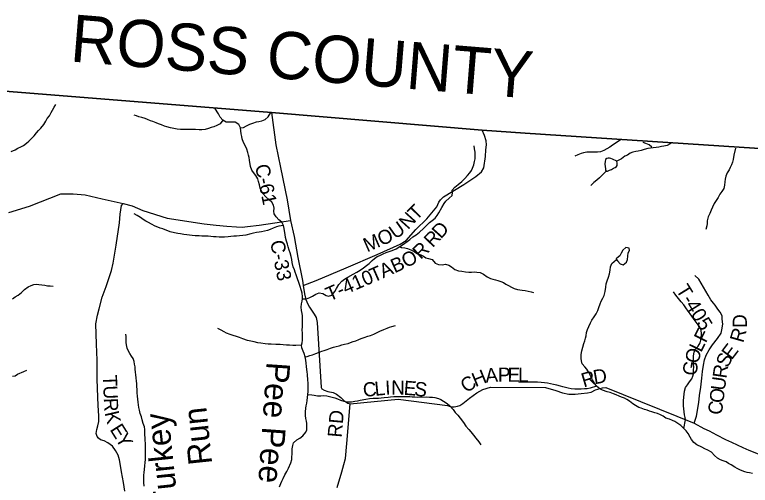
# Model space of a CAD drawing. Extents: x 1578669 to 1989827, y 208020 to 553079.
# Drawn here: x 1795443 to 1811019, y 424095 to 434061 of the extents above; entities that cross this region are included whole.
import ezdxf

# ---------------------------------------------------------------- set-up
doc = ezdxf.new("R2010")
doc.units = 0
for name, color, linetype in [('GM_X_Adjacent_County', 7, 'Continuous'), ('GM_X_Adjacent_County_Text', 7, 'Continuous'), ('GM_X_County', 7, 'Continuous'), ('GM_X_County_Road', 7, 'Continuous'), ('GM_X_County_Road_Text', 7, 'Continuous'), ('GM_X_Minor_Lake', 7, 'Continuous'), ('GM_X_Minor_River', 7, 'Continuous'), ('GM_X_Minor_River_Text', 7, 'Continuous'), ('GM_X_Township', 7, 'Continuous'), ('GM_X_Township_Road', 7, 'Continuous'), ('GM_X_Township_Road_Text', 7, 'Continuous')]:
    doc.layers.add(name, color=color, linetype=linetype)

msp = doc.modelspace()

# ---------------------------------------------------------------- linework, layer by layer
at = {"layer": 'GM_X_Adjacent_County'}
msp.add_lwpolyline([(1849204, 428734), (1845065, 429025), (1838434, 429477), (1835610, 429648), (1834516, 429711), (1833780, 429762), (1832918, 429813), (1828657, 430067), (1826767, 430168), (1822276, 430466), (1822111, 430472), (1818512, 430701), (1815260, 430933), (1812296, 431154), (1806251, 431556), (1805343, 431619), (1800878, 431987), (1794614, 432491)], dxfattribs=at)
at = {"layer": 'GM_X_County'}
msp.add_lwpolyline([(1794614, 432491), (1800878, 431987), (1805343, 431619), (1806251, 431556), (1812296, 431154), (1815260, 430933), (1818512, 430701), (1822111, 430472), (1822276, 430466), (1826767, 430168), (1828657, 430067), (1832918, 429813), (1833780, 429762), (1834516, 429711), (1835610, 429648), (1838434, 429477), (1845065, 429025), (1849204, 428734)], dxfattribs=at)
at = {"layer": 'GM_X_County_Road'}
for points in [[(1800878, 431987), (1800971, 431306), (1801072, 430825), (1801210, 430141), (1801283, 429700)], [(1795320, 429874), (1795754, 430005), (1796421, 430266), (1796599, 430271), (1796679, 430271), (1796937, 430244), (1797298, 430164), (1797739, 430061), (1797927, 430013), (1798153, 429916), (1798670, 429755), (1799457, 429631), (1799711, 429604), (1799934, 429584), (1800136, 429567), (1800260, 429559), (1800374, 429574), (1800621, 429604), (1801283, 429700)], [(1801283, 429700), (1801358, 429363), (1801440, 428920), (1801537, 428435), (1801549, 428324), (1801580, 428148), (1801606, 428032), (1801650, 427929), (1801685, 427865), (1801785, 427719), (1801823, 427648), (1801851, 427542), (1801935, 426167), (1801949, 426141), (1801999, 426109), (1802073, 426080), (1802183, 426062), (1802255, 426024), (1802351, 425953), (1802413, 425891), (1802495, 425835), (1802545, 425821), (1803561, 425916), (1804604, 425786), (1804680, 425756), (1804750, 425754), (1804817, 425770), (1804869, 425787), (1804931, 425829), (1805076, 425939), (1805226, 426051), (1805359, 426125), (1805517, 426172), (1806685, 426163), (1806901, 426106), (1807046, 426054), (1807180, 426025), (1807308, 426023), (1807438, 426036), (1807572, 426056), (1807651, 426070), (1807745, 426116), (1807837, 426145), (1807893, 426159), (1807962, 426163), (1809833, 425408), (1810039, 425299), (1810149, 425251), (1810301, 425164), (1810495, 425068), (1810621, 425009), (1810859, 424898), (1810991, 424838), (1811295, 424721)], [(1802269, 424048), (1802370, 424380), (1802412, 424536), (1802449, 424660), (1802474, 424983), (1802545, 425821)]]:
    msp.add_lwpolyline(points, dxfattribs=at)
at = {"layer": 'GM_X_Minor_Lake'}
for points in [[(1808190, 430963), (1808166, 430977), (1808132, 430987), (1808100, 430999), (1808069, 431016), (1808039, 431022), (1808011, 431020), (1807979, 431015), (1807955, 430997), (1807948, 430951), (1807942, 430903), (1807943, 430843), (1807955, 430803), (1807953, 430769), (1807971, 430751), (1807996, 430747), (1808037, 430769), (1808081, 430784), (1808125, 430808), (1808159, 430825), (1808187, 430847), (1808201, 430871), (1808203, 430917)], [(1808203, 430917), (1808190, 430963)], [(1808205, 428847), (1808261, 428782), (1808328, 428764), (1808401, 428821), (1808419, 428875), (1808424, 428948), (1808436, 429016), (1808463, 429068), (1808453, 429118), (1808387, 429130), (1808321, 429077), (1808288, 429008), (1808258, 428958), (1808196, 428907)], [(1808196, 428907), (1808179, 428893), (1808177, 428887), (1808186, 428878), (1808205, 428847)]]:
    msp.add_lwpolyline(points, dxfattribs=at)
at = {"layer": 'GM_X_Minor_River'}
for points in [[(1795371, 431162), (1795453, 431201), (1795511, 431232), (1795569, 431260), (1795631, 431293), (1795691, 431340), (1795742, 431380), (1795794, 431431), (1795852, 431495), (1795901, 431558), (1795949, 431609), (1795997, 431661), (1796058, 431736), (1796100, 431806), (1796133, 431861), (1796177, 431921), (1796214, 431988), (1796244, 432042), (1796279, 432101), (1796315, 432161)], [(1800378, 431146), (1800358, 431216), (1800327, 431274), (1800284, 431354), (1800260, 431432), (1800251, 431484), (1800239, 431540), (1800232, 431600), (1800227, 431666), (1800189, 431738), (1800112, 431783), (1800046, 431784), (1799976, 431784), (1799922, 431789), (1799851, 431826), (1799796, 431892), (1799756, 431962), (1799683, 432085)], [(1800227, 431666), (1800284, 431670), (1800349, 431705), (1800421, 431742), (1800487, 431766), (1800561, 431791), (1800613, 431802), (1800679, 431816), (1800749, 431845), (1800813, 431898), (1800867, 431990)], [(1799851, 431826), (1799794, 431750), (1799726, 431717), (1799662, 431688), (1799604, 431670), (1799548, 431651), (1799476, 431628), (1799406, 431620), (1799352, 431621), (1799269, 431628), (1799215, 431630), (1799143, 431631), (1799071, 431629), (1799017, 431628), (1798950, 431629), (1798882, 431639), (1798742, 431669), (1798667, 431687), (1798615, 431700), (1798551, 431726), (1798490, 431751), (1798436, 431775), (1798371, 431798), (1798319, 431816), (1798257, 431841), (1798202, 431861), (1798138, 431882), (1798074, 431902), (1798020, 431919), (1797969, 431933)], [(1808273, 431409), (1808157, 431332), (1808105, 431295), (1808043, 431258), (1807985, 431220), (1807920, 431189), (1807850, 431160), (1807781, 431150), (1807709, 431151), (1807657, 431153), (1807607, 431152), (1807555, 431148), (1807487, 431137), (1807437, 431122), (1807365, 431094), (1807303, 431065)], [(1809337, 431332), (1809262, 431290), (1809190, 431276), (1809138, 431267), (1809086, 431255), (1809024, 431246), (1808964, 431239), (1808904, 431235), (1808848, 431226), (1808774, 431209), (1808710, 431189), (1808646, 431172), (1808596, 431162), (1808529, 431147), (1808477, 431128), (1808416, 431090), (1808362, 431063), (1808292, 431008), (1808190, 430963)], [(1808932, 431253), (1808875, 431303), (1808809, 431334), (1808748, 431354)], [(1801536, 428043), (1801621, 428042), (1801693, 428071), (1801747, 428099), (1801822, 428144), (1801892, 428173), (1801967, 428159), (1802041, 428116), (1802091, 428103), (1802157, 428125), (1802221, 428196), (1802256, 428262), (1802306, 428349), (1802369, 428418), (1802427, 428461), (1802495, 428505), (1802611, 428565), (1802691, 428609), (1802756, 428650), (1802826, 428701), (1802894, 428748), (1802946, 428792), (1803009, 428855), (1803065, 428900), (1803117, 428938), (1803175, 428965), (1803243, 428996), (1803311, 429022), (1803374, 429047), (1803438, 429068), (1803520, 429102), (1803596, 429149), (1803674, 429202), (1803754, 429261), (1803809, 429300), (1803875, 429354), (1803945, 429403), (1804015, 429456), (1804096, 429533), (1804162, 429600), (1804229, 429660), (1804281, 429701), (1804349, 429756), (1804390, 429812), (1804426, 429867), (1804485, 429979), (1804535, 430062), (1804572, 430113), (1804646, 430177), (1804704, 430230), (1804711, 430294), (1804705, 430348), (1804762, 430407), (1804834, 430462), (1804911, 430527), (1804975, 430593), (1805033, 430658), (1805080, 430711), (1805118, 430761), (1805140, 430813), (1805165, 430882), (1805182, 430956), (1805192, 431012), (1805195, 431099), (1805191, 431149), (1805180, 431219), (1805172, 431287)], [(1810704, 431232), (1810672, 431084), (1810654, 430995), (1810641, 430935), (1810625, 430881), (1810596, 430824), (1810570, 430774), (1810528, 430714), (1810499, 430641), (1810484, 430579), (1810478, 430525), (1810471, 430448), (1810457, 430378), (1810416, 430314), (1810378, 430261), (1810337, 430187), (1810297, 430130), (1810257, 430064), (1810216, 429985), (1810189, 429919), (1810161, 429850), (1810130, 429782), (1810108, 429699), (1810103, 429641), (1810097, 429587), (1810076, 429509)], [(1801313, 424692), (1801319, 424762), (1801318, 424814), (1801320, 424868), (1801331, 424938), (1801349, 424997), (1801416, 425058), (1801480, 425096), (1801546, 425143), (1801609, 425218), (1801627, 425268), (1801632, 425346), (1801630, 425402), (1801619, 425456), (1801609, 425512), (1801598, 425574), (1801600, 425649), (1801611, 425729), (1801618, 425779), (1801628, 425837), (1801635, 425891), (1801645, 425958), (1801652, 426016), (1801660, 426080), (1801659, 426198), (1801654, 426264), (1801650, 426325), (1801641, 426441), (1801636, 426497), (1801630, 426551), (1801623, 426609), (1801615, 426679), (1801606, 426745), (1801593, 426815), (1801569, 426887), (1801550, 426939), (1801521, 427009), (1801515, 427061), (1801531, 427115), (1801538, 427169), (1801536, 427235), (1801535, 427320), (1801532, 427390), (1801536, 427450), (1801537, 427516), (1801539, 427572), (1801538, 427632), (1801534, 427682), (1801527, 427736), (1801519, 427796), (1801512, 427868), (1801519, 427939), (1801531, 427993), (1801536, 428043), (1801536, 428095), (1801527, 428161), (1801513, 428213), (1801480, 428325), (1801459, 428393), (1801432, 428471), (1801404, 428555), (1801385, 428607), (1801365, 428659), (1801342, 428721), (1801321, 428815), (1801309, 428875), (1801294, 428941), (1801273, 429015), (1801253, 429075), (1801232, 429142), (1801216, 429204), (1801197, 429268), (1801180, 429340), (1801172, 429406), (1801159, 429484), (1801152, 429534), (1801134, 429600), (1801099, 429666), (1801037, 429720), (1800978, 429783), (1800937, 429847), (1800933, 429901), (1800936, 429963), (1800924, 430029), (1800885, 430089), (1800830, 430143), (1800760, 430204), (1800699, 430272), (1800662, 430335), (1800640, 430387), (1800623, 430461), (1800608, 430527), (1800592, 430585), (1800547, 430653), (1800496, 430717), (1800466, 430770), (1800437, 430848), (1800416, 430984), (1800405, 431036), (1800395, 431086), (1800378, 431146)], [(1807971, 430751), (1807878, 430656), (1807826, 430605), (1807773, 430558), (1807705, 430506), (1807643, 430447)], [(1801134, 429600), (1801036, 429581), (1800984, 429571), (1800916, 429542), (1800850, 429514), (1800796, 429493), (1800734, 429476), (1800668, 429464), (1800616, 429459), (1800562, 429449), (1800498, 429434), (1800442, 429419), (1800334, 429390), (1800270, 429382), (1800203, 429377), (1800141, 429374), (1800081, 429370), (1800019, 429363), (1799961, 429359), (1799885, 429352), (1799829, 429351), (1799770, 429353), (1799706, 429354), (1799650, 429360), (1799598, 429365), (1799540, 429369), (1799488, 429372), (1799407, 429373), (1799347, 429377), (1799265, 429380), (1799199, 429385), (1799145, 429391), (1799084, 429400), (1799026, 429408), (1798954, 429419), (1798896, 429429), (1798825, 429442), (1798735, 429463), (1798683, 429483), (1798632, 429502), (1798576, 429524), (1798522, 429543), (1798471, 429563), (1798419, 429586), (1798338, 429628), (1798274, 429663), (1798220, 429691), (1798163, 429726), (1798105, 429764), (1798036, 429811), (1797974, 429847)], [(1803596, 429149), (1803634, 429128), (1803705, 429122), (1803759, 429109), (1803831, 429085), (1803902, 429048), (1803970, 428995), (1804045, 428977), (1804101, 428948), (1804152, 428912), (1804208, 428901), (1804280, 428877), (1804349, 428800), (1804420, 428774), (1804494, 428763), (1804564, 428778), (1804638, 428760), (1804689, 428719), (1804763, 428665), (1804842, 428640), (1804914, 428633), (1804988, 428618), (1805057, 428606), (1805113, 428609), (1805179, 428613), (1805229, 428612), (1805297, 428599), (1805370, 428565), (1805446, 428510), (1805515, 428476), (1805565, 428461), (1805624, 428445), (1805676, 428432), (1805738, 428414), (1805792, 428391), (1805845, 428355), (1805899, 428328), (1805962, 428292), (1806016, 428263), (1806088, 428245), (1806139, 428238), (1806191, 428230), (1806251, 428219), (1806315, 428208), (1806376, 428194), (1806426, 428177)], [(1807597, 427460), (1807637, 427539), (1807664, 427591), (1807710, 427662), (1807753, 427728), (1807789, 427797), (1807814, 427863), (1807840, 427940), (1807865, 427998), (1807897, 428057), (1807922, 428117), (1807948, 428201), (1807957, 428290), (1807970, 428362), (1807992, 428426), (1808019, 428505), (1808041, 428575), (1808052, 428649), (1808059, 428720), (1808085, 428792), (1808185, 428880)], [(1795397, 428044), (1795455, 428085), (1795518, 428121), (1795588, 428178), (1795650, 428239), (1795727, 428298), (1795789, 428328), (1795847, 428347), (1795899, 428352), (1795955, 428348), (1796014, 428343), (1796078, 428333), (1796140, 428322), (1796190, 428316), (1796259, 428309)], [(1809615, 425299), (1809646, 425482), (1809639, 425534), (1809629, 425584), (1809618, 425650), (1809610, 425716), (1809607, 425778), (1809605, 425834), (1809604, 425887), (1809610, 425965), (1809617, 426025), (1809628, 426091), (1809650, 426166), (1809691, 426220), (1809733, 426283), (1809781, 426353), (1809802, 426404), (1809814, 426458), (1809819, 426532), (1809822, 426606), (1809820, 426664), (1809819, 426730), (1809815, 426785), (1809816, 426837), (1809828, 426913), (1809861, 426975), (1809915, 427044), (1809956, 427111), (1809974, 427169), (1809981, 427225), (1809987, 427299), (1809976, 427385), (1809939, 427467), (1809874, 427549), (1809834, 427610), (1809785, 427678), (1809744, 427730), (1809706, 427782), (1809655, 427851), (1809613, 427915), (1809558, 427979), (1809497, 428054), (1809442, 428124), (1809392, 428189)], [(1801593, 426815), (1801639, 426822), (1801695, 426842), (1801749, 426859), (1801817, 426887), (1801873, 426910), (1801943, 426935), (1801999, 426953), (1802057, 426974), (1802131, 426999), (1802195, 427019), (1802249, 427036), (1802313, 427050), (1802371, 427067), (1802427, 427082), (1802501, 427100), (1802555, 427117), (1802611, 427140), (1802663, 427158), (1802729, 427185), (1802781, 427203), (1802841, 427226), (1802919, 427253), (1802975, 427271), (1803045, 427298), (1803105, 427323), (1803177, 427359), (1803259, 427396), (1803329, 427423), (1803382, 427444), (1803432, 427458), (1803506, 427481)], [(1811069, 424348), (1811001, 424359), (1810951, 424368), (1810901, 424380), (1810814, 424415), (1810740, 424453), (1810689, 424482), (1810617, 424528), (1810560, 424559), (1810506, 424589), (1810445, 424614), (1810387, 424634), (1810325, 424667), (1810262, 424726), (1810195, 424796), (1810117, 424841), (1810060, 424867), (1809992, 424900), (1809891, 424951), (1809826, 425005), (1809778, 425062), (1809745, 425114), (1809703, 425190), (1809660, 425248), (1809615, 425299), (1809551, 425363), (1809488, 425406), (1809420, 425444), (1809369, 425465), (1809307, 425493), (1809230, 425518), (1809176, 425556), (1809116, 425587), (1809055, 425613), (1808999, 425632), (1808934, 425654), (1808884, 425667), (1808834, 425685), (1808780, 425700), (1808709, 425726), (1808659, 425741), (1808586, 425782), (1808530, 425822), (1808461, 425879), (1808405, 425911), (1808354, 425937), (1808294, 425964), (1808244, 425986), (1808177, 426013), (1808121, 426032), (1808053, 426058), (1807992, 426073), (1807892, 426112), (1807835, 426140), (1807763, 426193), (1807720, 426259), (1807675, 426331), (1807636, 426411), (1807602, 426482), (1807561, 426552), (1807516, 426604), (1807460, 426671), (1807447, 426729), (1807439, 426783), (1807440, 426868), (1807451, 426940), (1807473, 427018), (1807498, 427101), (1807516, 427153), (1807529, 427209), (1807543, 427263), (1807554, 427328), (1807572, 427394), (1807597, 427460)], [(1797802, 427246), (1797793, 427296)], [(1801515, 427061), (1801399, 427056), (1801329, 427057), (1801262, 427062), (1801198, 427066), (1801124, 427071), (1801062, 427074), (1800969, 427080), (1800875, 427083), (1800809, 427086), (1800743, 427093), (1800656, 427103), (1800590, 427114), (1800514, 427133), (1800445, 427149), (1800373, 427164), (1800275, 427195), (1800206, 427223), (1800140, 427246), (1800067, 427269), (1800005, 427291), (1799931, 427320), (1799880, 427346), (1799812, 427383), (1799747, 427419)], [(1798184, 424076), (1798176, 424154), (1798175, 424227), (1798178, 424309), (1798186, 424369), (1798191, 424427), (1798199, 424509), (1798204, 424580), (1798210, 424644), (1798213, 424712), (1798212, 424770), (1798214, 424858), (1798213, 424925), (1798211, 424987), (1798208, 425041), (1798204, 425105), (1798201, 425159), (1798201, 425221), (1798196, 425275), (1798188, 425333), (1798165, 425407), (1798142, 425483), (1798126, 425543), (1798101, 425615), (1798084, 425683), (1798070, 425743), (1798061, 425801), (1798055, 425857), (1798050, 425921), (1798043, 425985), (1798039, 426055), (1798034, 426127), (1798032, 426190), (1798027, 426254), (1798023, 426304), (1798016, 426372), (1798009, 426432), (1798003, 426494), (1797996, 426552), (1797990, 426606), (1797981, 426664), (1797971, 426716), (1797950, 426778), (1797918, 426830), (1797879, 426884), (1797851, 426937), (1797824, 426997), (1797807, 427069), (1797803, 427119), (1797804, 427183), (1797802, 427246)], [(1795397, 426403), (1795451, 426415), (1795505, 426446), (1795633, 426507), (1795699, 426536)], [(1807763, 426193), (1807631, 426150), (1807563, 426137), (1807507, 426135), (1807438, 426132), (1807380, 426129), (1807304, 426129), (1807228, 426140), (1807161, 426155), (1807107, 426167), (1807051, 426180), (1807001, 426194), (1806926, 426215), (1806850, 426233), (1806792, 426246), (1806723, 426257), (1806659, 426267), (1806593, 426274), (1806513, 426277), (1806453, 426281), (1806386, 426280), (1806330, 426282), (1806260, 426279), (1806186, 426278), (1806120, 426274)], [(1801652, 426016), (1801733, 426013), (1801787, 426005), (1801857, 425990), (1801925, 425992), (1801987, 425995), (1802054, 425988), (1802108, 425976), (1802164, 425963), (1802221, 425947), (1802275, 425926), (1802345, 425896), (1802412, 425877), (1802476, 425866), (1802572, 425866), (1802642, 425877), (1802704, 425884), (1802760, 425896), (1802876, 425917), (1802957, 425930), (1803035, 425937), (1803085, 425940), (1803145, 425944), (1803205, 425951), (1803267, 425957), (1803349, 425964), (1803401, 425969), (1803472, 425973), (1803536, 425974), (1803610, 425977), (1803678, 425977), (1803742, 425976), (1803808, 425973), (1803859, 425967), (1803917, 425966), (1803977, 425964), (1804171, 425966), (1804226, 425965), (1804288, 425963), (1804340, 425958), (1804416, 425936), (1804469, 425911), (1804523, 425879), (1804598, 425828), (1804648, 425786), (1804729, 425701), (1804772, 425639), (1804826, 425582), (1804879, 425514), (1804944, 425426), (1804999, 425347), (1805060, 425279), (1805100, 425225), (1805161, 425158), (1805208, 425092), (1805270, 425017), (1805315, 424951)], [(1801050, 424066), (1801075, 424132), (1801097, 424183), (1801125, 424237), (1801166, 424316), (1801207, 424390), (1801239, 424459), (1801290, 424571), (1801308, 424640), (1801313, 424692)]]:
    msp.add_lwpolyline(points, dxfattribs=at)
at = {"layer": 'GM_X_Township'}
msp.add_lwpolyline([(1794614, 432491), (1800878, 431987), (1805343, 431619), (1806251, 431556), (1812296, 431154), (1812748, 423763), (1812981, 420551), (1813183, 417646), (1813169, 417495), (1813101, 417318), (1811396, 411352), (1811003, 410233), (1810653, 409191), (1809037, 404233), (1808867, 403681), (1808758, 403152), (1808680, 402775), (1808603, 402344), (1807250, 395261), (1804835, 395344), (1793085, 395748)], dxfattribs=at)
at = {"layer": 'GM_X_Township_Road'}
for points in [[(1801549, 428324), (1801827, 428430), (1802459, 428700), (1803116, 428985), (1803605, 429204), (1803732, 429282), (1803939, 429514), (1804168, 429739), (1804379, 429991), (1804421, 430089), (1804456, 430139), (1804526, 430203), (1804952, 430462), (1805208, 430632), (1805329, 430736), (1805375, 430818), (1805414, 431056), (1805421, 431200), (1805433, 431303), (1805426, 431388), (1805392, 431505), (1805343, 431619)], [(1797776, 423969), (1797743, 424151), (1797705, 424380), (1797682, 424516), (1797662, 424633), (1797632, 424733), (1797579, 424833), (1797511, 424922), (1797417, 424996), (1797337, 425034), (1797261, 425061), (1797217, 425091), (1797189, 425129), (1797167, 425191), (1797181, 425275), (1797204, 425358), (1797224, 425446), (1797226, 425566), (1797213, 425784), (1797201, 425959), (1797191, 426346), (1797186, 426746), (1797177, 427081), (1797158, 427514), (1797196, 427700), (1797233, 427829), (1797298, 428076), (1797379, 428308), (1797492, 428641), (1797529, 428797), (1797588, 429179), (1797664, 429653), (1797674, 429836), (1797707, 430018), (1797739, 430061)], [(1809833, 425408), (1809881, 425556), (1809928, 425849), (1809943, 425999), (1809969, 426173), (1809992, 426362), (1810010, 426502), (1810031, 426640), (1810053, 426752), (1810086, 426852), (1810150, 426962), (1810222, 427072), (1810327, 427206), (1810402, 427316), (1810418, 427386), (1810436, 427505), (1810427, 427613), (1810425, 427681), (1810383, 427759), (1810335, 427822), (1810273, 427912), (1810237, 427950), (1810185, 428024), (1810124, 428125), (1810026, 428293), (1809928, 428460), (1809844, 428540)]]:
    msp.add_lwpolyline(points, dxfattribs=at)

# ---------------------------------------------------------------- texts
at = {"layer": 'GM_X_Adjacent_County_Text'}
msp.add_text('ROSS COUNTY', height=1000, rotation=355.3774, dxfattribs=at).set_placement((1796599, 433073))
at = {"layer": 'GM_X_County_Road_Text'}
for s, rotation, p in [('C-61', 281.7823, (1800530, 430865)), ('C-33', 281.0414, (1800850, 429257)), ('H', 22.2749, (1805198, 426172)), ('A', 4.6717, (1805419, 426267)), ('P', 359.8907, (1805675, 426288)), ('E', 359.7429, (1805878, 426288)), ('L', 359.7441, (1806102, 426287)), ('R', 16.429, (1807492, 426166)), ('D', 10.1654, (1807720, 426233)), ('C', 35.4537, (1805013, 426038)), ('C', 5.3764, (1802830, 425966)), ('L', 5.3764, (1803075, 425989)), ('I', 3.3804, (1803296, 426010)), ('N', 359.3883, (1803414, 426017)), ('E', 355.3963, (1803672, 426014)), ('S', 353.4002, (1803893, 425996)), ('RD', 85.0738, (1802366, 425099))]:
    msp.add_text(s, height=300, rotation=rotation, dxfattribs=at).set_placement(p)
at = {"layer": 'GM_X_Minor_River_Text'}
for s, rotation, p in [('Pee Pee', 265.9803, (1800780, 426717)), ('Run', 95.9994, (1799626, 424551)), ('Turkey', 95.9992, (1798907, 423617))]:
    msp.add_text(s, height=500, rotation=rotation, dxfattribs=at).set_placement(p)
at = {"layer": 'GM_X_Township_Road_Text'}
for s, rotation, p in [('T', 45.1606, (1803947, 429688)), ('N', 47.8531, (1803773, 429495)), ('U', 35.2155, (1803503, 429295)), ('D', 48.0662, (1804469, 429300)), ('O', 23.6879, (1803204, 429157)), ('R', 46.5098, (1804293, 429114)), ('M', 23.5639, (1802905, 429026)), ('R', 43.562, (1804039, 428866)), ('O', 27.1557, (1803728, 428691)), ('B', 24.137, (1803487, 428583)), ('T', 23.6392, (1803038, 428385)), ('A', 23.7164, (1803244, 428476)), ('T-410', 23.3083, (1802107, 427985)), ('T-405', 301.7018, (1809435, 428235)), ('D', 90.3679, (1810948, 427429)), ('F', 62.8633, (1810077, 427094)), ('R', 73.8954, (1810867, 427099)), ('O', 74.3043, (1809912, 426654)), ('L', 63.6132, (1809978, 426894)), ('E', 52.6441, (1810624, 426736)), ('S', 63.9173, (1810543, 426568)), ('G', 81.9008, (1809877, 426403)), ('R', 81.6888, (1810515, 426347)), ('T', 272.3492, (1797308, 426427)), ('U', 82.2171, (1810479, 426087)), ('U', 272.3488, (1797317, 426203)), ('O', 83.3932, (1810449, 425826)), ('R', 272.3307, (1797328, 425939)), ('C', 81.7164, (1810412, 425573)), ('K', 283.1632, (1797346, 425632)), ('E', 302.185, (1797448, 425277)), ('Y', 299.8773, (1797565, 425090))]:
    msp.add_text(s, height=300, rotation=rotation, dxfattribs=at).set_placement(p)

doc.saveas('drawing.dxf')
